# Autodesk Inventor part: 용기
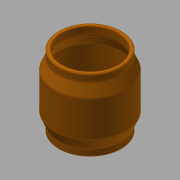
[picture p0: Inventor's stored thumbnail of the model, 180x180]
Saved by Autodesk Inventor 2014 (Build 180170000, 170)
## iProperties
Created: 2018-01
Part Number: 용기
Material: ABS 플라스틱
Document SubType Name: Modeling
Designer: mduedu
Density: 1 g/cm^3
Appearance: Orange
Author: mduedu
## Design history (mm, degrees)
sketch "스케치1"
  geometry: L1 (0, 0)-(-35, 0); L2 (-35, 0)-(-35, 8); L3 (-35, 8)-(-40, 20); L4 (-40, 20)-(-40, 60); L5 (-40, 60)-(-35, 72); L6 (-35, 72)-(-35, 80); L7 (-35, 80)-(0, 80); L8 (0, 80)-(0, 0)
  constraints: 16 end point, 3 collinear, 3 parallel, 1 horizontal, 1 perpendicular
  dimensions: "d0" = 8 distance of L1.end L2.end; "d2" = 70 diameter of L2 L8; "d3" = 20 distance from line of L3.end L1; "d4" = 60 distance from line of L4.end L1; "d5" = 20 distance from line of L4.end L7; "d6" = 80 diameter of L4 L8
revolve "회전1" sketch "스케치1" stored, may be unused: angle "d7" = 90 deg
fillet "모깎기1" dims "d8" = 3
feature "쉘1" dims "d9" = 4
fillet "모깎기2" dims "d10" = 1
chamfer "모따기1" distance "d11" = 0.5; stored, may be unused: second distance "d12" = 2, angle "d13" = 45 deg
node "솔리드1"
